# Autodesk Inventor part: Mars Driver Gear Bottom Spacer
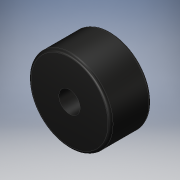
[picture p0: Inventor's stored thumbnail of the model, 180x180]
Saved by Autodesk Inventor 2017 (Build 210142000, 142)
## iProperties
Created: 2016-07
Part Number: Mars Driver Gear Bottom Spacer
Material: Generic
Document SubType Name: Modeling
Designer: Stan
Density: 1 g/cm^3
Appearance: Glossy - Black
Author: Stan
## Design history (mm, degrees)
sketch "Sketch1"
  geometry: C1 r 12.7 at (0, 0); C2 r 3.302 at (0, 0); 1 further point
  constraints: 2 centre point, 2 coincident
  dimensions: "d0" = 25.4 diameter of C1; "d1" = 6.604 diameter of C2
extrude "Extrusion1" new body sketch "Sketch1" distance "d2" = 12.7; taper "d3" = 0 deg
fillet "Fillet1" dims "d4" = 0.79375
body "Solid1"
